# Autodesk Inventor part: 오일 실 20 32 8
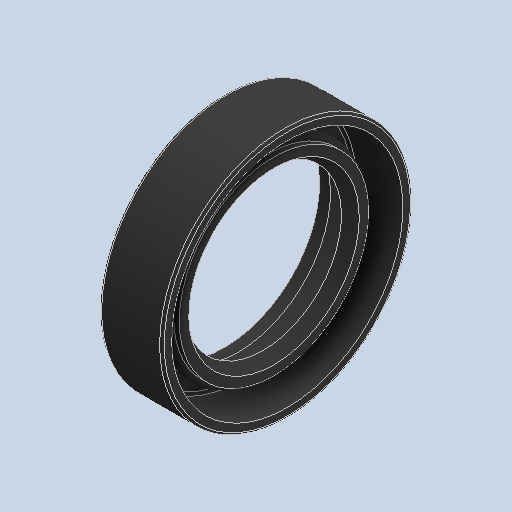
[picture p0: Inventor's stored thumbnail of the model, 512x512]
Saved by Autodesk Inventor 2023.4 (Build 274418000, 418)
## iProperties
Created: 2024-11
Part Number: 오일 실 20 32 8
Material: 고무
Description: 오일-실
Document SubType Name: Modeling
Designer: EDU
Density: 0.93 g/cm^3
Appearance: 기본값
Author: jhkim
Sending System: Autodesk Inventor 2025
Preprocessor: ST-DEVELOPER v20
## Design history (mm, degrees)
feature "Solid1"
node "솔리드1"
